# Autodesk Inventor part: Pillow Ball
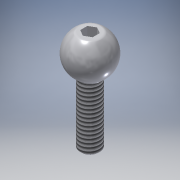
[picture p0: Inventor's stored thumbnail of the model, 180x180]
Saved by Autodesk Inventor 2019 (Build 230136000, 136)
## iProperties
Shininess: 55.0
Compacted: True
Length Units: 11272
Angle Units: 11279
Time Units: 11290
Mass Units: 11286
Length Display Precision: 4
Angle Display Precision: 2
Company: Autodesk
Created: 2000-05
Part Number: Pillow Ball
Project: Inventor Samples
User Status: IN PROGRESS
Document SubType Name: Modeling
Designer: Autodesk, Inc.
Density: 8.08 g/cm^3
Mass: 3.34543 g
Surface Area: 3.76075 cm^2
Volume: 0.414039 cm^3
Material: Stainless Steel
Appearance: Light Grey
Density: 0.0
Volumn: 0.0
Area: 0.0
PropertySet Name: Model Information
Control State: 0
Master: False
Checked Out: False
Checked Out Date: 2018-05-30
Last Check In Date: 2018-05-30
Author: Autodesk, Inc.
Revision Number: A
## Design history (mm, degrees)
node "Revolution1" dims "d4" = 90 deg
  sketch "Sketch2"
    geometry: L1 (-19.414, -28.533)-(-19.414, -8.531); L2 (-19.414, -28.533)-(-21.319, -28.533); L3 (-21.319, -28.533)-(-21.319, -16.32); A1 r 4.128 centre (-19.414, -12.658) between (-19.414, -8.531) and (-21.319, -16.32)
    constraints: 6 end point, 2 perpendicular, 2 point on circle, 1 centre point, 1 point on line, 1 vertical, 1 other
    dimensions: "d1" = 8.255 diameter of A1; "d2" = 3.81 diameter of L3 L1; "d3" = 15.875 distance from line of A1.centre L2
node "Fillet1" dims "d5" = 0.381
node "Chamfer1" dims "d6" = 0.381, "d7" = 0.381, "d17" = 45 deg
node "Extrusion1" dims "d9" = 25.4, "d10" = 0
  sketch "Sketch3"
    geometry: L1 (-21.478, -9.084)-(-17.35, -9.084); A1 r 4.127 centre (-19.414, -12.658) between (-17.321, -16.216) and (-21.507, -16.216) reference
    constraints: 2 end point, 2 point on circle, 1 horizontal
    dimensions: "d8" = 4.1275 distance of L1.start L1.end
node "Fillet2" dims "d11" = 0.8128
node "Extrusion2" dims "d13" = 2.54, "d14" = 0
  sketch "Sketch4"
    geometry: L1 (-1.191, 0.687)-(-1.191, -0.687); L2 (-1.191, -0.687)-(0, -1.375); L3 (0, -1.375)-(1.191, -0.687); L4 (1.191, -0.687)-(1.191, 0.687); L5 (1.191, 0.687)-(0, 1.375); L6 (0, 1.375)-(-1.191, 0.687); C1 r 1.833 at (0, 0) reference; C2 r 1.191 at (0, 0)
    constraints: 12 end point, 6 tangent, 4 equal length, 1 centre point, 1 coincident, 1 parallel, 1 vertical
    dimensions: "d12" = 2.38125 diameter of C2
thread "Thread1" dims "d15" = 25.4, "d16" = 0
body "Solid1"
